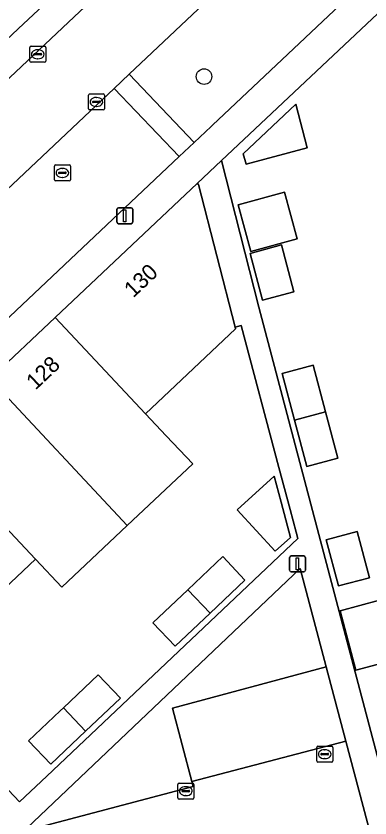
# Model space of a CAD drawing. Extents: x 162542 to 163147, y 380779 to 381521.
# Drawn here: x 162706.3 to 162728.5, y 381232.9 to 381283.2 of the extents above; entities that cross this region are included whole.
import ezdxf

# ---------------------------------------------------------------- set-up
doc = ezdxf.new("R2010")
doc.units = 0
for name, color, linetype in [('IMGEO_Boom', 7, 'Continuous'), ('IMGEO_Erf', 7, 'Continuous'), ('IMGEO_Groenvoorziening', 7, 'Continuous'), ('IMGEO_Kolk', 7, 'Continuous'), ('IMGEO_Lichtmast', 7, 'Continuous'), ('IMGEO_Pand', 7, 'Continuous'), ('IMGEO_Pand_nummerreeks', 7, 'Continuous'), ('IMGEO_Parkeervlak_open', 7, 'Continuous'), ('IMGEO_Rijbaan_lokaal_open', 7, 'Continuous'), ('IMGEO_Rioolput', 7, 'Continuous'), ('IMGEO_Voetpad_open', 7, 'Continuous')]:
    doc.layers.add(name, color=color, linetype=linetype)

msp = doc.modelspace()

# ---------------------------------------------------------------- linework, layer by layer
at = {"layer": 'IMGEO_Boom'}
msp.add_circle((162718.121, 381279.403), 0.489, dxfattribs=at)
at = {"layer": 'IMGEO_Erf'}
msp.add_lwpolyline([(162744.981, 381229.839), (162743.62, 381234.957), (162740.117, 381234.033), (162738.611, 381239.742), (162739.779, 381240.048), (162738.373, 381245.277), (162740.708, 381245.905), (162739.452, 381250.629), (162737.132, 381250.014), (162735.602, 381255.723), (162737.931, 381256.347), (162736.681, 381261.046), (162734.34, 381260.415), (162732.908, 381265.788), (162731.477, 381271.162), (162730.045, 381276.535), (162736.954, 381278.376), (162734.296, 381288.323), (162719.215, 381274.137), (162721.568, 381264.953), (162735.925, 381210.607)], dxfattribs=at)
for points in [[(162720.761, 381273.919), (162720.588, 381274.566), (162723.878, 381277.678), (162724.607, 381274.943)], [(162721.051, 381268.436), (162720.258, 381271.36), (162723.184, 381272.152), (162723.976, 381269.228)], [(162723.756, 381265.91), (162721.801, 381265.381), (162721.022, 381268.314), (162722.976, 381268.843)], [(162724.022, 381250.433), (162723.915, 381250.834), (162723.533, 381252.257), (162722.828, 381254.89), (162720.445, 381263.784), (162720.077, 381263.689), (162720.106, 381263.577), (162714.45, 381258.258), (162715.742, 381256.883), (162717.408, 381255.111), (162713.298, 381251.249), (162709.189, 381247.387), (162707.53, 381249.144), (162703.604, 381245.444), (162699.677, 381241.743), (162699.606, 381241.818), (162699.315, 381241.544), (162706.532, 381233.918), (162708.241, 381235.532)], [(162724.575, 381254.944), (162723.8, 381257.863), (162723.024, 381260.781), (162724.975, 381261.31), (162725.753, 381258.382), (162726.527, 381255.472)], [(162720.211, 381252.226), (162722.521, 381254.347), (162722.955, 381252.721), (162723.547, 381250.502), (162722.591, 381249.636)], [(162728.518, 381247.977), (162726.564, 381247.458), (162725.794, 381250.355), (162727.745, 381250.883)], [(162719.3, 381249.303), (162720.69, 381247.831), (162718.499, 381245.754), (162716.308, 381243.677), (162714.915, 381245.147), (162717.106, 381247.224)], [(162731.357, 381243.162), (162727.653, 381242.178), (162726.662, 381245.909), (162730.367, 381246.893)], [(162711.482, 381241.895), (162712.876, 381240.422), (162710.683, 381238.348), (162708.49, 381236.274), (162707.088, 381237.741), (162709.084, 381239.628), (162709.289, 381239.822)]]:
    msp.add_lwpolyline(points, close=True, dxfattribs=at)
at = {"layer": 'IMGEO_Groenvoorziening'}
for points in [[(162745.949, 381302.07), (162741.952, 381306.416), (162713.421, 381279.554), (162717.504, 381275.272), (162718.576, 381276.281), (162718.648, 381276.35)], [(162716.558, 381274.381), (162712.475, 381278.663), (162708.323, 381274.754), (162691.959, 381259.343), (162696.039, 381255.065)], [(162725.799, 381242.395), (162724.166, 381248.556), (162706.988, 381232.279), (162707.019, 381232.142), (162707.144, 381232.175), (162717.44, 381234.879), (162717.359, 381235.188), (162716.135, 381239.802)]]:
    msp.add_lwpolyline(points, close=True, dxfattribs=at)
at = {"layer": 'IMGEO_Kolk'}
for p, q in [((162707.18, 381280.376), (162707.18, 381281.228)), ((162707.255, 381281.302), (162708.107, 381281.302)), ((162707.668, 381281.082), (162707.693, 381281.082)), ((162708.181, 381281.228), (162708.181, 381280.376)), ((162707.439, 381280.796), (162707.439, 381280.808)), ((162707.877, 381280.759), (162707.479, 381280.759)), ((162707.482, 381280.845), (162707.88, 381280.845)), ((162707.923, 381280.808), (162707.923, 381280.796)), ((162708.107, 381280.302), (162707.255, 381280.302)), ((162707.691, 381280.522), (162707.666, 381280.522)), ((162710.863, 381277.385), (162710.863, 381278.237)), ((162710.938, 381278.311), (162711.79, 381278.311)), ((162711.351, 381278.091), (162711.376, 381278.091)), ((162711.864, 381278.237), (162711.864, 381277.385)), ((162711.122, 381277.805), (162711.122, 381277.817)), ((162711.56, 381277.768), (162711.162, 381277.768)), ((162711.165, 381277.854), (162711.563, 381277.854)), ((162711.606, 381277.817), (162711.606, 381277.805)), ((162711.79, 381277.311), (162710.938, 381277.311)), ((162711.374, 381277.531), (162711.349, 381277.531)), ((162725.2, 381236.483), (162725.2, 381237.335)), ((162725.275, 381237.409), (162726.127, 381237.409)), ((162726.201, 381237.335), (162726.201, 381236.483)), ((162725.459, 381236.903), (162725.459, 381236.915)), ((162725.897, 381236.866), (162725.499, 381236.866)), ((162725.502, 381236.952), (162725.9, 381236.952)), ((162725.688, 381237.189), (162725.713, 381237.189)), ((162725.943, 381236.915), (162725.943, 381236.903)), ((162726.127, 381236.409), (162725.275, 381236.409)), ((162725.711, 381236.629), (162725.686, 381236.629)), ((162716.476, 381234.166), (162716.476, 381235.018)), ((162716.551, 381235.092), (162717.403, 381235.092)), ((162716.964, 381234.872), (162716.989, 381234.872)), ((162717.477, 381235.018), (162717.477, 381234.166)), ((162716.735, 381234.586), (162716.735, 381234.598)), ((162717.173, 381234.549), (162716.775, 381234.549)), ((162716.778, 381234.635), (162717.176, 381234.635)), ((162716.987, 381234.312), (162716.962, 381234.312)), ((162717.219, 381234.598), (162717.219, 381234.586)), ((162717.403, 381234.092), (162716.551, 381234.092))]:
    msp.add_line(p, q, dxfattribs=at)
for points in [[(162707.18, 381280.376), (162707.18, 381281.228)], [(162707.255, 381281.302), (162708.107, 381281.302)], [(162708.181, 381281.228), (162708.181, 381280.376)], [(162708.107, 381280.302), (162707.255, 381280.302)], [(162710.863, 381277.385), (162710.863, 381278.237)], [(162710.938, 381278.311), (162711.79, 381278.311)], [(162711.864, 381278.237), (162711.864, 381277.385)], [(162711.79, 381277.311), (162710.938, 381277.311)], [(162725.2, 381236.483), (162725.2, 381237.335)], [(162725.275, 381237.409), (162726.127, 381237.409)], [(162726.201, 381237.335), (162726.201, 381236.483)], [(162726.127, 381236.409), (162725.275, 381236.409)], [(162716.476, 381234.166), (162716.476, 381235.018)], [(162716.551, 381235.092), (162717.403, 381235.092)], [(162717.477, 381235.018), (162717.477, 381234.166)], [(162717.403, 381234.092), (162716.551, 381234.092)]]:
    msp.add_lwpolyline(points, dxfattribs=at)
for centre, radius, start, end in [((162707.257, 381281.226), 0.0765, 91.552, 178.448), ((162707.257, 381281.226), 0.0765, 91.552, 178.448), ((162708.105, 381281.226), 0.0765, 1.552, 88.448), ((162708.105, 381281.226), 0.0765, 1.552, 88.448), ((162707.479, 381280.805), 0.0403, 85.8775, 175.7526), ((162707.476, 381280.795), 0.0366, 178.938, 274.7102), ((162707.88, 381280.802), 0.043, 264.8664, 352.4533), ((162707.884, 381280.807), 0.0386, 1.7309, 96.639), ((162707.257, 381280.378), 0.0765, 181.552, 268.448), ((162707.257, 381280.378), 0.0765, 181.552, 268.448), ((162708.105, 381280.378), 0.0765, 271.552, 358.448), ((162708.105, 381280.378), 0.0765, 271.552, 358.448), ((162710.94, 381278.235), 0.0765, 91.552, 178.448), ((162710.94, 381278.235), 0.0765, 91.552, 178.448), ((162711.788, 381278.235), 0.0765, 1.552, 88.448), ((162711.788, 381278.235), 0.0765, 1.552, 88.448), ((162711.162, 381277.814), 0.0403, 85.8775, 175.7526), ((162711.159, 381277.804), 0.0366, 178.938, 274.7102), ((162711.563, 381277.811), 0.043, 264.8664, 352.4533), ((162711.567, 381277.816), 0.0386, 1.7309, 96.639), ((162710.94, 381277.387), 0.0765, 181.552, 268.448), ((162710.94, 381277.387), 0.0765, 181.552, 268.448), ((162711.788, 381277.387), 0.0765, 271.552, 358.448), ((162711.788, 381277.387), 0.0765, 271.552, 358.448), ((162725.277, 381237.333), 0.0765, 91.552, 178.448), ((162725.277, 381237.333), 0.0765, 91.552, 178.448), ((162726.125, 381237.333), 0.0765, 1.552, 88.448), ((162726.125, 381237.333), 0.0765, 1.552, 88.448), ((162725.499, 381236.912), 0.0403, 85.8775, 175.7526), ((162725.496, 381236.902), 0.0366, 178.938, 274.7102), ((162725.9, 381236.909), 0.043, 264.8664, 352.4533), ((162725.904, 381236.914), 0.0386, 1.7309, 96.639), ((162725.277, 381236.485), 0.0765, 181.552, 268.448), ((162725.277, 381236.485), 0.0765, 181.552, 268.448), ((162726.125, 381236.485), 0.0765, 271.552, 358.448), ((162726.125, 381236.485), 0.0765, 271.552, 358.448), ((162716.553, 381235.016), 0.0765, 91.552, 178.448), ((162716.553, 381235.016), 0.0765, 91.552, 178.448), ((162717.401, 381235.016), 0.0765, 1.552, 88.448), ((162717.401, 381235.016), 0.0765, 1.552, 88.448), ((162716.775, 381234.595), 0.0403, 85.8775, 175.7526), ((162716.772, 381234.585), 0.0366, 178.938, 274.7102), ((162717.176, 381234.592), 0.043, 264.8664, 352.4533), ((162717.18, 381234.597), 0.0386, 1.7309, 96.639), ((162716.553, 381234.168), 0.0765, 181.552, 268.448), ((162716.553, 381234.168), 0.0765, 181.552, 268.448), ((162717.401, 381234.168), 0.0765, 271.552, 358.448), ((162717.401, 381234.168), 0.0765, 271.552, 358.448)]:
    msp.add_arc(centre, radius, start, end, dxfattribs=at)
for centre, major_axis, ratio, start_param, end_param in [((162707.667, 381280.802), (-0.387, 0.002), 0.722429, 4.712389, 7.853982), ((162707.692, 381280.802), (-0.39, 0.002), 0.717154, 1.570796, 4.712389), ((162711.35, 381277.811), (-0.387, 0.002), 0.722429, 4.712389, 7.853982), ((162711.375, 381277.811), (-0.39, 0.002), 0.717154, 1.570796, 4.712389), ((162725.687, 381236.909), (-0.387, 0.002), 0.722429, 4.712389, 7.853982), ((162725.712, 381236.909), (-0.39, 0.002), 0.717154, 1.570796, 4.712389), ((162716.963, 381234.592), (-0.387, 0.002), 0.722429, 4.712389, 7.853982), ((162716.988, 381234.592), (-0.39, 0.002), 0.717154, 1.570796, 4.712389)]:
    msp.add_ellipse(centre, major_axis=major_axis, ratio=ratio, start_param=start_param, end_param=end_param, dxfattribs=at)
at = {"layer": 'IMGEO_Lichtmast'}
for p, q in [((162712.65, 381270.279), (162712.65, 381271.079)), ((162712.65, 381271.079), (162712.65, 381270.279)), ((162712.75, 381271.179), (162713.54, 381271.179)), ((162713.54, 381271.179), (162712.75, 381271.179)), ((162713.64, 381271.079), (162713.64, 381270.279)), ((162713.64, 381270.279), (162713.64, 381271.079)), ((162713.54, 381270.179), (162712.75, 381270.179)), ((162712.75, 381270.179), (162713.54, 381270.179)), ((162723.493, 381248.443), (162723.493, 381249.243)), ((162723.493, 381249.243), (162723.493, 381248.443)), ((162723.593, 381249.343), (162724.383, 381249.343)), ((162724.383, 381249.343), (162723.593, 381249.343)), ((162724.483, 381249.243), (162724.483, 381248.443)), ((162724.483, 381248.443), (162724.483, 381249.243)), ((162724.383, 381248.343), (162723.593, 381248.343)), ((162723.593, 381248.343), (162724.383, 381248.343))]:
    msp.add_line(p, q, dxfattribs=at)
for points in [[(162713.07, 381271.054), (162713.22, 381271.054), (162713.22, 381270.304), (162713.07, 381270.304), (162713.07, 381271.054)], [(162723.913, 381249.218), (162724.063, 381249.218), (162724.063, 381248.468), (162723.913, 381248.468), (162723.913, 381249.218)]]:
    msp.add_lwpolyline(points, dxfattribs=at)
for centre, start, end in [((162712.75, 381271.079), 90, 180), ((162712.75, 381271.079), 90, 180), ((162713.54, 381271.079), 0, 90), ((162713.54, 381271.079), 360, 90), ((162712.75, 381270.279), 180, 270), ((162712.75, 381270.279), 180, 270), ((162713.54, 381270.279), 270, 0), ((162713.54, 381270.279), 270, 0), ((162723.593, 381249.243), 90, 180), ((162723.593, 381249.243), 90, 180), ((162724.383, 381249.243), 0, 90), ((162724.383, 381249.243), 360, 90), ((162723.593, 381248.443), 180, 270), ((162723.593, 381248.443), 180, 270), ((162724.383, 381248.443), 270, 0), ((162724.383, 381248.443), 270, 0)]:
    msp.add_arc(centre, 0.1, start, end, dxfattribs=at)
at = {"layer": 'IMGEO_Pand'}
for points in [[(162723.878, 381277.678), (162720.588, 381274.566), (162720.761, 381273.919), (162724.607, 381274.943)], [(162717.763, 381272.634), (162717.694, 381272.707), (162708.769, 381264.304), (162714.45, 381258.258), (162720.106, 381263.577), (162720.077, 381263.689)], [(162723.184, 381272.152), (162720.258, 381271.36), (162721.051, 381268.436), (162723.976, 381269.228)], [(162722.976, 381268.843), (162721.022, 381268.314), (162721.801, 381265.381), (162723.756, 381265.91)], [(162714.45, 381258.258), (162708.769, 381264.304), (162704.663, 381260.438), (162713.298, 381251.249), (162717.408, 381255.111), (162715.742, 381256.883)], [(162723.024, 381260.781), (162723.8, 381257.863), (162725.753, 381258.382), (162724.975, 381261.31)], [(162704.663, 381260.438), (162700.536, 381256.552), (162707.53, 381249.144), (162709.189, 381247.387), (162713.298, 381251.249)], [(162725.753, 381258.382), (162723.8, 381257.863), (162724.575, 381254.944), (162726.527, 381255.472)], [(162700.536, 381256.552), (162696.614, 381252.86), (162703.604, 381245.444), (162707.53, 381249.144)], [(162722.521, 381254.347), (162720.211, 381252.226), (162722.591, 381249.636), (162723.547, 381250.502), (162722.955, 381252.721)], [(162725.794, 381250.355), (162726.564, 381247.458), (162728.518, 381247.977), (162727.745, 381250.883)], [(162720.69, 381247.831), (162719.3, 381249.303), (162717.106, 381247.224), (162718.499, 381245.754)], [(162718.499, 381245.754), (162717.106, 381247.224), (162714.915, 381245.147), (162716.308, 381243.677)], [(162730.367, 381246.893), (162726.662, 381245.909), (162727.653, 381242.178), (162731.357, 381243.162)], [(162712.876, 381240.422), (162711.482, 381241.895), (162709.289, 381239.822), (162710.683, 381238.348)], [(162710.683, 381238.348), (162709.289, 381239.822), (162709.084, 381239.628), (162707.088, 381237.741), (162708.49, 381236.274)]]:
    msp.add_lwpolyline(points, close=True, dxfattribs=at)
at = {"layer": 'IMGEO_Parkeervlak_open'}
for points in [[(162716.657, 381289.445), (162715.361, 381290.782), (162710.868, 381286.543), (162706.458, 381282.394), (162689.195, 381266.132), (162690.48, 381264.817), (162709.97, 381283.154)], [(162725.799, 381242.395), (162716.135, 381239.802), (162717.359, 381235.188), (162727.036, 381237.729)]]:
    msp.add_lwpolyline(points, close=True, dxfattribs=at)
at = {"layer": 'IMGEO_Rijbaan_lokaal_open'}
msp.add_lwpolyline([(162716.657, 381289.445), (162709.97, 381283.154), (162690.48, 381264.817), (162688.879, 381263.31), (162679.694, 381254.668), (162679.674, 381254.69), (162679.585, 381254.601), (162683.136, 381251.037), (162684.99, 381252.78), (162690.848, 381258.296), (162691.959, 381259.343), (162708.323, 381274.754), (162712.475, 381278.663), (162713.421, 381279.554), (162741.952, 381306.416)], dxfattribs=at)
msp.add_lwpolyline([(162728.656, 381231.579), (162727.036, 381237.729), (162717.359, 381235.188), (162717.44, 381234.879), (162707.144, 381232.175), (162707.019, 381232.142), (162703.666, 381231.209), (162700.747, 381230.44), (162700.456, 381230.763), (162700.677, 381230.974), (162688.475, 381243.889), (162691.953, 381247.17), (162691.301, 381247.857), (162679.601, 381236.83), (162680.253, 381236.137), (162683.764, 381239.482), (162697.438, 381224.879), (162697.666, 381225.113), (162698.805, 381223.893), (162699.779, 381224.12), (162699.849, 381223.847)], close=True, dxfattribs=at)
at = {"layer": 'IMGEO_Rioolput'}
for p, q in [((162708.725, 381272.937), (162708.725, 381273.789)), ((162708.8, 381273.863), (162709.652, 381273.863)), ((162709.213, 381273.643), (162709.238, 381273.643)), ((162709.726, 381273.789), (162709.726, 381272.937)), ((162708.984, 381273.357), (162708.984, 381273.369)), ((162709.422, 381273.32), (162709.024, 381273.32)), ((162709.027, 381273.406), (162709.425, 381273.406)), ((162709.236, 381273.083), (162709.211, 381273.083)), ((162709.468, 381273.369), (162709.468, 381273.357)), ((162709.652, 381272.863), (162708.8, 381272.863))]:
    msp.add_line(p, q, dxfattribs=at)
for points in [[(162708.725, 381272.937), (162708.725, 381273.789)], [(162708.8, 381273.863), (162709.652, 381273.863)], [(162709.726, 381273.789), (162709.726, 381272.937)], [(162709.652, 381272.863), (162708.8, 381272.863)]]:
    msp.add_lwpolyline(points, dxfattribs=at)
for centre, radius, start, end in [((162708.802, 381273.787), 0.0765, 91.552, 178.448), ((162708.802, 381273.787), 0.0765, 91.552, 178.448), ((162709.65, 381273.787), 0.0765, 1.552, 88.448), ((162709.65, 381273.787), 0.0765, 1.552, 88.448), ((162709.024, 381273.366), 0.0403, 85.8775, 175.7526), ((162709.021, 381273.356), 0.0366, 178.938, 274.7102), ((162709.425, 381273.363), 0.043, 264.8664, 352.4533), ((162709.429, 381273.368), 0.0386, 1.7309, 96.639), ((162708.802, 381272.939), 0.0765, 181.552, 268.448), ((162708.802, 381272.939), 0.0765, 181.552, 268.448), ((162709.65, 381272.939), 0.0765, 271.552, 358.448), ((162709.65, 381272.939), 0.0765, 271.552, 358.448)]:
    msp.add_arc(centre, radius, start, end, dxfattribs=at)
for centre, major_axis, ratio, start_param, end_param in [((162709.212, 381273.363), (-0.387, 0.002), 0.722429, 4.712389, 7.853982), ((162709.237, 381273.363), (-0.39, 0.002), 0.717154, 1.570796, 4.712389)]:
    msp.add_ellipse(centre, major_axis=major_axis, ratio=ratio, start_param=start_param, end_param=end_param, dxfattribs=at)
at = {"layer": 'IMGEO_Voetpad_open'}
for points in [[(162745.949, 381302.07), (162718.648, 381276.35), (162718.576, 381276.281), (162717.504, 381275.272), (162716.558, 381274.381), (162696.039, 381255.065), (162694.927, 381254.018), (162686.27, 381245.869), (162682.176, 381250.134), (162677.801, 381246.021), (162681.879, 381241.745), (162673.979, 381234.315), (162669.948, 381238.638)], [(162667.173, 381225.141), (162678.234, 381235.545), (162679.601, 381236.83), (162691.301, 381247.857), (162692.684, 381249.159), (162696.614, 381252.86), (162700.536, 381256.552), (162704.663, 381260.438), (162708.769, 381264.304), (162717.694, 381272.707), (162719.215, 381274.137), (162734.296, 381288.323)], [(162677.312, 381254.938), (162678.414, 381255.976), (162687.636, 381264.663), (162689.195, 381266.132), (162706.458, 381282.394), (162710.868, 381286.543)], [(162735.925, 381210.607), (162721.568, 381264.953), (162719.215, 381274.137), (162717.694, 381272.707), (162717.763, 381272.634), (162720.077, 381263.689), (162720.445, 381263.784), (162722.828, 381254.89), (162723.533, 381252.257), (162723.915, 381250.834), (162724.022, 381250.433), (162708.241, 381235.532), (162706.532, 381233.918), (162699.315, 381241.544), (162699.606, 381241.818), (162692.684, 381249.159), (162691.301, 381247.857), (162691.953, 381247.17), (162704.173, 381234.294), (162705.462, 381232.918), (162703.666, 381231.209)], [(162706.988, 381232.279), (162724.166, 381248.556), (162725.799, 381242.395), (162727.036, 381237.729), (162728.656, 381231.579)]]:
    msp.add_lwpolyline(points, dxfattribs=at)
msp.add_lwpolyline([(162713.421, 381279.554), (162712.475, 381278.663), (162716.558, 381274.381), (162717.504, 381275.272)], close=True, dxfattribs=at)

# ---------------------------------------------------------------- texts
at = {"layer": 'IMGEO_Pand_nummerreeks'}
for s, p in [('130', (162713.678, 381265.492)), ('128', (162707.533, 381259.706))]:
    msp.add_text(s, height=1, rotation=43.2755, dxfattribs=at).set_placement(p)

doc.saveas('drawing.dxf')
